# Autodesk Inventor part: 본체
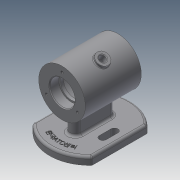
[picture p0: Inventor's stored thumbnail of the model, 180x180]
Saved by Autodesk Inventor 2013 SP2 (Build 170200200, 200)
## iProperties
Created: 2022-02
Part Number: 본체
Material: Generic
Document SubType Name: Modeling
Designer: a
Density: 1 g/cm^3
Author: a
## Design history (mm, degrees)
sketch "스케치1"
  geometry: C1 r 30 at (0, 0); 1 further point
  constraints: 1 centre point, 1 coincident
  dimensions: "d0" = 60 diameter of C1
extrude "돌출1" new body sketch "스케치1" stored distance "d1" = 72; taper "d2" = 0 deg
sketch "스케치2"
  geometry: L1 (30, -36)-(-30, -36) reference; L2 (-30, -36)-(-30, 36) reference; L3 (-30, 36)-(30, 36) reference; L4 (30, 36)-(30, -36) reference; L5 (16, 36)-(16, 24); L6 (16, 24)-(14, 24); L7 (14, 24)-(14, 20); L8 (14, 20)-(25, 20); L9 (25, 20)-(25, -20); L10 (25, -20)-(14, -20); L11 (14, -20)-(14, -24); L12 (14, -24)-(16, -24); L13 (16, -24)-(16, -36); L14 (0, 36)-(0, -36); 1 further point
  constraints: 20 end point, 6 parallel, 3 perpendicular, 2 collinear, 2 midpoint, 2 point on line
  dimensions: "d3" = 32 diameter of L5 L14; "d5" = 28 diameter of L7 L14; "d6" = 40 distance of L8.end L9.end; "d7" = 28 diameter of L11 L14; "d8" = 32 diameter of L13 L14; "d9" = 12 distance of L5.start L5.end; "d10" = 50 diameter of L9 L14
revolve "회전1" sketch "스케치2" stored, may be unused: angle "d11" = 90 deg
fillet "모깎기1" dims "d12" = 3
fillet "모깎기2" dims "d13" = 0.3
chamfer "모따기1" distance "d14" = 1; stored, may be unused: second distance "d15" = 2, angle "d16" = 45 deg
sketch "스케치3"
  geometry: L1 (0, 0)-(0, 23); C1 r 17 at (0, 0) reference; 1 further point
  constraints: 2 end point, 1 coincident, 1 vertical
  dimensions: "d17" = 23 distance of L1.start L1.end
hole "구멍1" sketch "스케치3" at (0, 23) diameter "d18" = 3.242; stored, may be unused: countersink angle "d22" = 82 deg, drill point angle "d24" = 118 deg; dims "d19" = 8, "d20" = 3.023, "d21" = 2, "d23" = 10
node "작업 평면1"
sketch "스케치4"
  geometry: L1 (38, 35.496)-(38, -35.496); L2 (-38, 35.496)-(-38, -35.496); L3 (38, 0)-(-38, 0); A1 r 52 centre (0, 0) between (38, 35.496) and (-38, 35.496); A2 r 52 centre (0, 0) between (-38, -35.496) and (38, -35.496); 2 further points
  constraints: 6 end point, 4 point on circle, 3 midpoint, 2 centre point, 2 coincident, 1 parallel, 1 vertical
  dimensions: "d30" = 76 distance between parallel lines of L2 L1; "d32" = 52 radius of A2
extrude "돌출2" join sketch "스케치4" distance "d33" = 10; taper "d34" = 0 deg
sketch "스케치5"
  geometry: L1 (38, -35.496)-(38, 35.496) reference; L2 (-24, 0)-(24, 0); L3 (-24, -7.5)-(-24, 7.5); L4 (-19.5, -7.5)-(-19.5, 7.5); L5 (-28.5, -7.5)-(-28.5, 7.5); A1 r 52 centre (0, 0) between (-38, -35.496) and (38, -35.496) reference; A2 r 4.5 centre (-24, -7.5) between (-19.5, -7.5) and (-28.5, -7.5); A3 r 4.5 centre (-24, 7.5) between (-19.5, 7.5) and (-28.5, 7.5); 1 further point
  constraints: 8 end point, 4 point on circle, 3 coincident, 2 centre point, 2 midpoint, 2 perpendicular, 2 tangent
  dimensions: "d35" = 48 distance of L2.start L2.end; "d36" = 15 distance of L3.start L3.end; "d37" = 9 diameter of A2; "d38" = 9 diameter of A3; "d39" = 15 distance of L5.start L5.end; "d40" = 15 distance of L4.start L4.end
extrude "돌출3" cut sketch "스케치5" stored distance "d41" = 10; taper "d42" = 0 deg
fillet "모깎기3" dims "d43" = 3
fillet "모깎기4" dims "d44" = 3
sketch "스케치6"
  geometry: L1 (7, 26)-(-7, 26); L2 (-7, 26)-(-7, -26); L3 (-7, -26)-(7, -26); L4 (7, -26)-(7, 26); L5 (7, 26)-(-7, -26); L6 (-7, 26)-(7, -26); A1 r 49 centre (0, 0) between (-35, -34.293) and (35, -34.293) reference
  constraints: 12 end point, 2 midpoint, 2 parallel, 1 horizontal, 1 perpendicular
  dimensions: "d45" = 14 distance of L3.end L2.end; "d46" = 52 distance of L2.end L1.end
extrude "돌출4" join sketch "스케치6" stored distance "d47" = 10; taper "d48" = 0 deg
fillet "모깎기5" dims "d49" = 7
sketch "스케치7"
  geometry: L1 (7, -29.172)-(7, -52) reference; L2 (7, -52)-(19.5, -52) reference; L3 (19.5, -52)-(19.5, -62) reference; L4 (19.5, -62)-(-19.5, -62) reference; L5 (-19.5, -62)-(-19.5, -52) reference; L6 (-19.5, -52)-(-7, -52) reference; L7 (-7, -52)-(-7, -29.172) reference; L8 (38, -55)-(38, -62) reference; L9 (38, -62)-(28.5, -62) reference; L10 (28.5, -62)-(28.5, -52) reference; L11 (28.5, -52)-(35, -52) reference; L12 (-35, -52)-(-28.5, -52) reference; L13 (-28.5, -52)-(-28.5, -62) reference; L14 (-28.5, -62)-(-38, -62) reference; L15 (-38, -62)-(-38, -55) reference; L16 (0, 0)-(16.5, 28.579); L17 (0, 0)-(0, 30); C1 r 25 at (0, 0) reference; A1 r 30 centre (0, 0) between (7, -29.172) and (-7, -29.172) reference; A2 r 3 centre (35, -55) between (38, -55) and (35, -52) reference; A3 r 3 centre (-35, -55) between (-35, -52) and (-38, -55) reference; 2 further points
  constraints: 4 end point, 1 coincident, 1 point on circle
  dimensions: "d50" = 33 distance of L16.start L16.end; "d52" = 30 deg angle of L16 L17
  node "절단 모서리 투영2"
node "작업 평면2"
sketch "스케치8"
  geometry: C1 r 8 at (0, 0); 1 further point
  constraints: 1 centre point, 1 coincident
  dimensions: "d53" = 16 diameter of C1
extrude "돌출5" join sketch "스케치8" stored distance "d54" = 10; taper "d55" = 0 deg
sketch "스케치9"
  geometry: C1 r 8 at (0, 0) reference; C2 r 4 at (0, 0)
  constraints: 1 centre point, 1 coincident
  dimensions: "d56" = 8 diameter of C2
extrude "돌출6" cut sketch "스케치9" stored distance "d57" = 10; taper "d58" = 0 deg
fillet "모깎기6" dims "d59" = 1
fillet "모깎기7" dims "d60" = 1
fillet "모깎기8" dims "d61" = 3
sketch "스케치10"
  geometry: C1 r 42.5 at (0, 0); A1 r 49 centre (0, 0) between (35, 34.293) and (-35, 34.293) reference
  constraints: 1 centre point, 1 coincident, 1 other
  dimensions: "d62" = 85 diameter of C1
feature "엠보싱1" sketch "스케치10" dims "d64" = 0.5, "d65" = 0
node "솔리드1"
pattern_circular "원형 패턴1" dims angle "d26" = 360 deg
mirror "대칭1"
mirror "대칭2"
node "절단 모서리 투영1"
other parameters: "d28" = -62
